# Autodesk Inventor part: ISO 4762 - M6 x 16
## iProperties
Comments: To add or edit properties for Autodesk Inventor files, use iProperties.
Created: 2004-08
Part Number: ISO 4762 - M6 x 16
Vendor: Autodesk Inc.
Document SubType Name: Modeling
Designer: John Blackburn
Material: Default
Description: Hexagon Socket Head Cap Screw
Standard: ISO 4762
Size Designation: M6 x 16
Alert: To add or edit properties for Autodesk Inventor files, use iProperties.
Control State: 0
Master: False
Checked Out: False
Shininess: 64.0
Length Units: 11269
Angle Units: 11279
Time Units: 11290
Mass Units: 11283
Length Display Precision: 3
Angle Display Precision: 2
Compacted: True
EGR: 1
Density: 0.0
Volumn: 0.0
Area: 0.0
PropertySet Name: Model Information
Author: John Blackburn
Revision Number: 8
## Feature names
1. Body [Revolution]
2. Slot [Extrusion]
3. Fillet1
4. Chamfer1
